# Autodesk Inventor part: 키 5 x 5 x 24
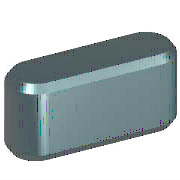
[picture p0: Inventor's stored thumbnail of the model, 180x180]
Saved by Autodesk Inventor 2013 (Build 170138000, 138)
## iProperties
IsCustomPart: 1
Created: 2012-02
Part Number: 키 5 x 5 x 24
Material: 강철, 연강
Description: 키 및 해당 키홈
Document SubType Name: Modeling
Standard: KS B 1311
Designer: mduedu
Standards Organization: KS
Language: ko-KR
Size Designation: 5 x 5 x 18
Categories: <MemberInstance><Categories><Category DisplayName="샤프트 부품" InternalName="7f7aeb1f-a693-4053-b835-cee3144e0d98" Mnemonic="SHFT"><Category DisplayName="키" Interna
Density: 7.86 g/cm^3
Mass: 4.43866 g
Surface Area: 4.72224 cm^2
Volume: 0.564716 cm^3
Author: mduedu
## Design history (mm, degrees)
workplane "Work Plane1"
workplane "Work Plane2"
sketch "스케치1"
  geometry: L1 (2.5, 2.5)-(21.5, 2.5); L2 (21.5, -2.5)-(2.5, -2.5); L3 (0, 8.9)-(0, -4.4) reference; L4 (-3.6, 0)-(21.6, 0) reference; L5 (24, 0)-(24, 7); A1 r 2.5 centre (2.5, 0) between (2.5, 2.5) and (2.5, -2.5); A2 r 2.5 centre (21.5, 0) between (21.5, -2.5) and (21.5, 2.5)
  constraints: 6 end point, 5 point on circle, 4 tangent, 3 point on line, 2 centre point, 1 horizontal, 1 parallel, 1 perpendicular
  dimensions: "d0" = 2.5 radius of A1 (= 0.5 x PB); "d13" = 2.5 radius of A2 (= 0.5 x PB); "d14" = 24 distance between parallel lines of L5 L3 (= NLG)
extrude "본체1" new body sketch "스케치1" taper "d3" = 0 deg; stored distance "d4" = 10
workplane "Work Plane3"
body "Solid1"
chamfer "모따기1" distance "d8" = 0.4 (= PHH); stored, may be unused: second distance "d9" = 0.4 (= PHH), angle "d15" = 45 deg
other parameters: "d1" = -3 (= -PNT), "d2" = 2 (= PH - PNT), "NLG" = 24 [user parameter; used in 3 equation terms], "PB" = 5 [user parameter; used in 2 equation terms], "PNT" = 3 [user parameter; used in 2 equation terms], "PH" = 5 [user parameter; used in 1 equation term], "PHH" = 0.4 [user parameter; used in 2 equation terms], "d10" = 0, "d16" = 0, "d17" = 0, "d18" = 0, "WDMIN" = 12 [user parameter], "PLB2" = 24 (= NLG) [user parameter], "WDMAX" = 17 [user parameter], "PLB1" = 24 (= NLG) [user parameter], "RR" = 0.16 [user parameter], "PUEB" = 2.3 [user parameter]
